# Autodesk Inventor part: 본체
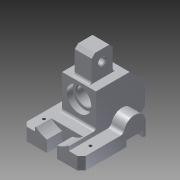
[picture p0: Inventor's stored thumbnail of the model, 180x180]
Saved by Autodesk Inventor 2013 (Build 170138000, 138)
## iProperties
Created: 2016-11
Part Number: 본체
Material: 알루미늄 6061
Document SubType Name: Modeling
Designer: Administrator
Density: 2.71 g/cm^3
Mass: 462.778 g
Surface Area: 317.348 cm^2
Volume: 170.767 cm^3
Author: Administrator
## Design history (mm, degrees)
sketch "스케치1"
  geometry: L1 (-35, 31.5)-(35, 31.5); L2 (35, 31.5)-(35, -31.5); L3 (35, -31.5)-(-35, -31.5); L4 (-35, -31.5)-(-35, 31.5); L5 (35, -31.5)-(-35, 31.5); 2 further points
  constraints: 10 end point, 2 parallel, 1 coincident, 1 horizontal, 1 midpoint, 1 perpendicular
  dimensions: "d0" = 63 distance of L3.end L1.start; "d2" = 70 distance of L1.start L1.end
extrude "돌출1" new body sketch "스케치1" distance "d3" = 15; taper "d4" = 0 deg
sketch "스케치2"
  geometry: L1 (0, 63)-(15, 63) reference; L2 (15, 63)-(15, 0) reference; L3 (15, 0)-(0, 0) reference; L4 (0, 0)-(0, 63) reference; L5 (7, 63)-(7, 73); L6 (7, 73)-(0, 73); L7 (0, 73)-(0, 76); L8 (0, 76)-(15, 76); L9 (15, 76)-(15, 63); L10 (7, 63)-(7, 53); L11 (7, 53)-(0, 53); L12 (15, 63)-(15, 50); L13 (15, 45.708)-(15, 0); L14 (0, 53)-(0, 0); L15 (15, 0)-(0, 0); A1 r 13 centre (15, 63) between (18.611, 50.512) and (6.693, 73); A2 r 5 centre (20, 45.708) between (18.611, 50.512) and (15, 45.708); 1 further point
  constraints: 22 end point, 5 perpendicular, 5 point on circle, 5 point on line, 3 collinear, 3 parallel, 2 centre point, 2 tangent, 1 coincident
  dimensions: "d5" = 3 distance of L6.end L7.end; "d7" = 7 distance of L5.end L6.end; "d9" = 20 distance between parallel lines of L11 L6; "d10" = 10 distance between parallel lines of L6 L1; "d11" = 13 radius of A1; "d12" = 5 radius of A2
  node "절단 모서리 투영1"
extrude "돌출2" cut sketch "스케치2" stored distance "d13" = 15; taper "d14" = 0 deg
extrude "돌출3" join sketch "스케치2" distance "d15" = 70; taper "d16" = 0 deg
extrude "돌출4" join sketch "스케치2" distance "d17" = 70; taper "d18" = 0 deg
sketch "스케치3"
  geometry: L1 (-31.5, 0)-(-31.5, 15) reference; L2 (-31.5, 15)-(14.208, 15) reference; L3 (44.5, 15)-(44.5, 0) reference; L4 (44.5, 0)-(41.5, 0) reference; L5 (41.5, 0)-(41.5, 7) reference; L6 (41.5, 7)-(21.5, 7) reference; L7 (21.5, 7)-(21.5, 0) reference; L8 (21.5, 0)-(-31.5, 0) reference; L9 (44.5, 12)-(54.5, 12); L10 (58.5, 16)-(58.5, 42); L11 (58.5, 42)-(40.5, 60); L12 (40.5, 60)-(33.5, 60); L13 (0.5, 60)-(0.5, 23); L14 (-2.5, 20)-(-31.5, 20); L15 (-31.5, 20)-(-31.5, 15); L16 (30.5, 63)-(30.5, 86); L17 (26.5, 90)-(9.5, 90); L18 (5.5, 86)-(5.5, 63); L19 (2.5, 60)-(0.5, 60); L20 (54.5, 12)-(58.5, 16); L21 (30.5, 86)-(26.5, 90); L22 (5.5, 86)-(9.5, 90); L23 (2.5, 60)-(33.5, 60); C1 r 4 at (18, 77); A1 r 5 centre (14.208, 20) between (14.208, 15) and (19.012, 18.611) reference; A2 r 13 centre (31.5, 15) between (44.5, 15) and (19.012, 18.611) reference; A3 r 3 centre (-2.5, 23) between (-2.5, 20) and (0.5, 23); A4 r 3 centre (33.5, 63) between (30.5, 63) and (33.5, 60); A5 r 3 centre (2.5, 63) between (2.5, 60) and (5.5, 63); 5 further points
  constraints: 30 end point, 11 point on line, 8 tangent, 6 perpendicular, 6 point on circle, 4 centre point, 4 parallel, 1 collinear
  dimensions: "d19" = 45 deg angle of L12 L11; "d20" = 90 distance between parallel lines of L1 L10; "d21" = 30 distance of point (58.5, 12) L10.end; "d22" = 48 distance between parallel lines of L9 L12; "d23" = 3 radius of A3; "d24" = 20 distance between parallel lines of L8 L14; "d25" = 58 distance between parallel lines of L10 L13; "d26" = 60 distance between parallel lines of L8 L12; "d27" = 25 distance of point (30.5, 90) point (5.5, 90); "d28" = 5 distance between parallel lines of L13 L18; "d29" = 90 distance between parallel lines of L17 L8; "d30" = 3 radius of A4; "d31" = 3 radius of A5; "d32" = 4 distance of L9.end point (58.5, 12); "d33" = 4 distance of L10.start point (58.5, 12) (= d32); "d34" = 4 distance of L16.end point (30.5, 90) (= d32); "d35" = 4 distance of L17.start point (30.5, 90) (= d34); "d36" = 4 distance of L18.start point (5.5, 90) (= d32); "d37" = 4 distance of L17.end point (5.5, 90) (= d36); "d38" = 77 distance from line of L8 C1.centre; "d39" = 8 diameter of C1; "d40" = 12.5 distance from line of L16 C1.centre
  node "절단 모서리 투영2"
extrude "돌출5" join sketch "스케치3" stored distance "d41" = 40; taper "d42" = 0 deg
extrude "돌출6" join sketch "스케치3" stored distance "d43" = 20; taper "d44" = 0 deg
sketch "스케치4"
  geometry: L1 (-15, -23)-(55, -23) reference; L2 (20, -23)-(20, 19); L3 (-15, -23)-(55, -23) reference; C1 r 10 at (20, 19); C2 r 14.5 at (20, 19)
  constraints: 2 centre point, 2 coincident, 2 end point, 1 perpendicular
  dimensions: "d45" = 20 diameter of C1; "d46" = 29 diameter of C2; "d47" = 42 distance from line of C1.centre L1
extrude "돌출7" cut sketch "스케치4" distance "d48" = 7; taper "d49" = 0 deg
extrude "돌출8" cut sketch "스케치4" stored distance "d50" = 7; taper "d51" = 0 deg
chamfer "모따기1" distance "d52" = 1; stored, may be unused: second distance "d53" = 2, angle "d54" = 45 deg
chamfer "모따기2" distance "d55" = 1; stored, may be unused: second distance "d56" = 2, angle "d57" = 45 deg
sketch "스케치5"
  geometry: L1 (0, 0)-(70, 0) reference; L2 (0, 0)-(70, 0) reference; L3 (29, 0)-(29, 13.627); L4 (41, 0)-(41, 13.627); L5 (35, -0.852)-(35, 42); L6 (29, 0)-(41, 0); C1 r 11 at (35, 42) reference; A1 r 29 centre (35, 42) between (29, 13.627) and (41, 13.627); 1 further point
  constraints: 8 end point, 2 parallel, 2 point on circle, 2 point on line, 1 centre point, 1 coincident, 1 collinear, 1 perpendicular, 1 other
  dimensions: "d58" = 29 radius of A1; "d60" = 12 distance between parallel lines of L4 L3
extrude "돌출9" cut sketch "스케치5" distance "d61" = 18; taper "d62" = 0 deg
sketch "스케치6"
  geometry: L1 (60, 40.5)-(60, 0.5) reference; L2 (56.5, 0.5)-(27.5, 0.5) reference; 2 further points
  constraints: 1 other
  dimensions: "d63" = 25 distance from line of L2 point (42, 25.5); "d64" = 18 distance from line of L1 point (42, 25.5)
feature "엠보싱1" sketch "스케치6" dims "d65" = 0.5, "d66" = 0
chamfer "모따기3" distance "d67" = 5; stored, may be unused: second distance "d68" = 2, angle "d69" = 45 deg
sketch "스케치7"
  geometry: L1 (35, 21.5)-(35, -26.5) reference; L2 (-35, -26.5)-(-35, 21.5) reference; L3 (-6, -31.5)-(-30, -31.5) reference; L4 (30, -31.5)-(6, -31.5) reference; L5 (-27.5, -13.5)-(27.5, -13.5); L6 (0, 0)-(0, -30.747)
  constraints: 4 end point, 2 parallel, 1 perpendicular, 1 symmetric about line
  dimensions: "d70" = 55 distance of L5.start L5.end; "d72" = 18 distance from line of L3 L5.start
hole "구멍1" sketch "스케치7" at (27.5, -13.5), (-27.5, -13.5) diameter "d73" = 3.459; stored, may be unused: countersink angle "d77" = 90 deg, drill point angle "d79" = 118 deg; dims "d74" = 5.984, "d75" = 4, "d76" = 2, "d78" = 8
node "솔리드1"
